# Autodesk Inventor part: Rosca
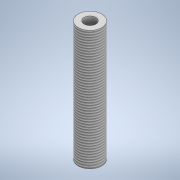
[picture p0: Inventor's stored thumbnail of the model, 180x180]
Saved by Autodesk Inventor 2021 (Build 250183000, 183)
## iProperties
Created: 2021-02
Part Number: Rosca
Material: Genérico
Document SubType Name: Modeling
Designer: ATOUZA
Density: 1 g/cm^3
Appearance: Valor por defecto
Author: ATOUZA
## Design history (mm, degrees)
sketch "Boceto1"
  geometry: C1 r 5 at (0, 0); 1 further point
  constraints: 1 centre point, 1 coincident
  dimensions: "d0" = 10 diameter of C1
extrude "Extrusión1" new body sketch "Boceto1" distance "d1" = 51; taper "d2" = 0 deg
feature "Rosca1" dims "d3" = 51, "d4" = 0
sketch "Boceto2"
  geometry: C1 r 2.5 at (0, 0); 1 further point
  constraints: 1 centre point, 1 coincident
  dimensions: "d5" = 5 diameter of C1
extrude "Extrusión2" cut sketch "Boceto2" extent not by distance; stored distance "d6" = 0; taper "d7" = 0 deg
node "Sólido1"
